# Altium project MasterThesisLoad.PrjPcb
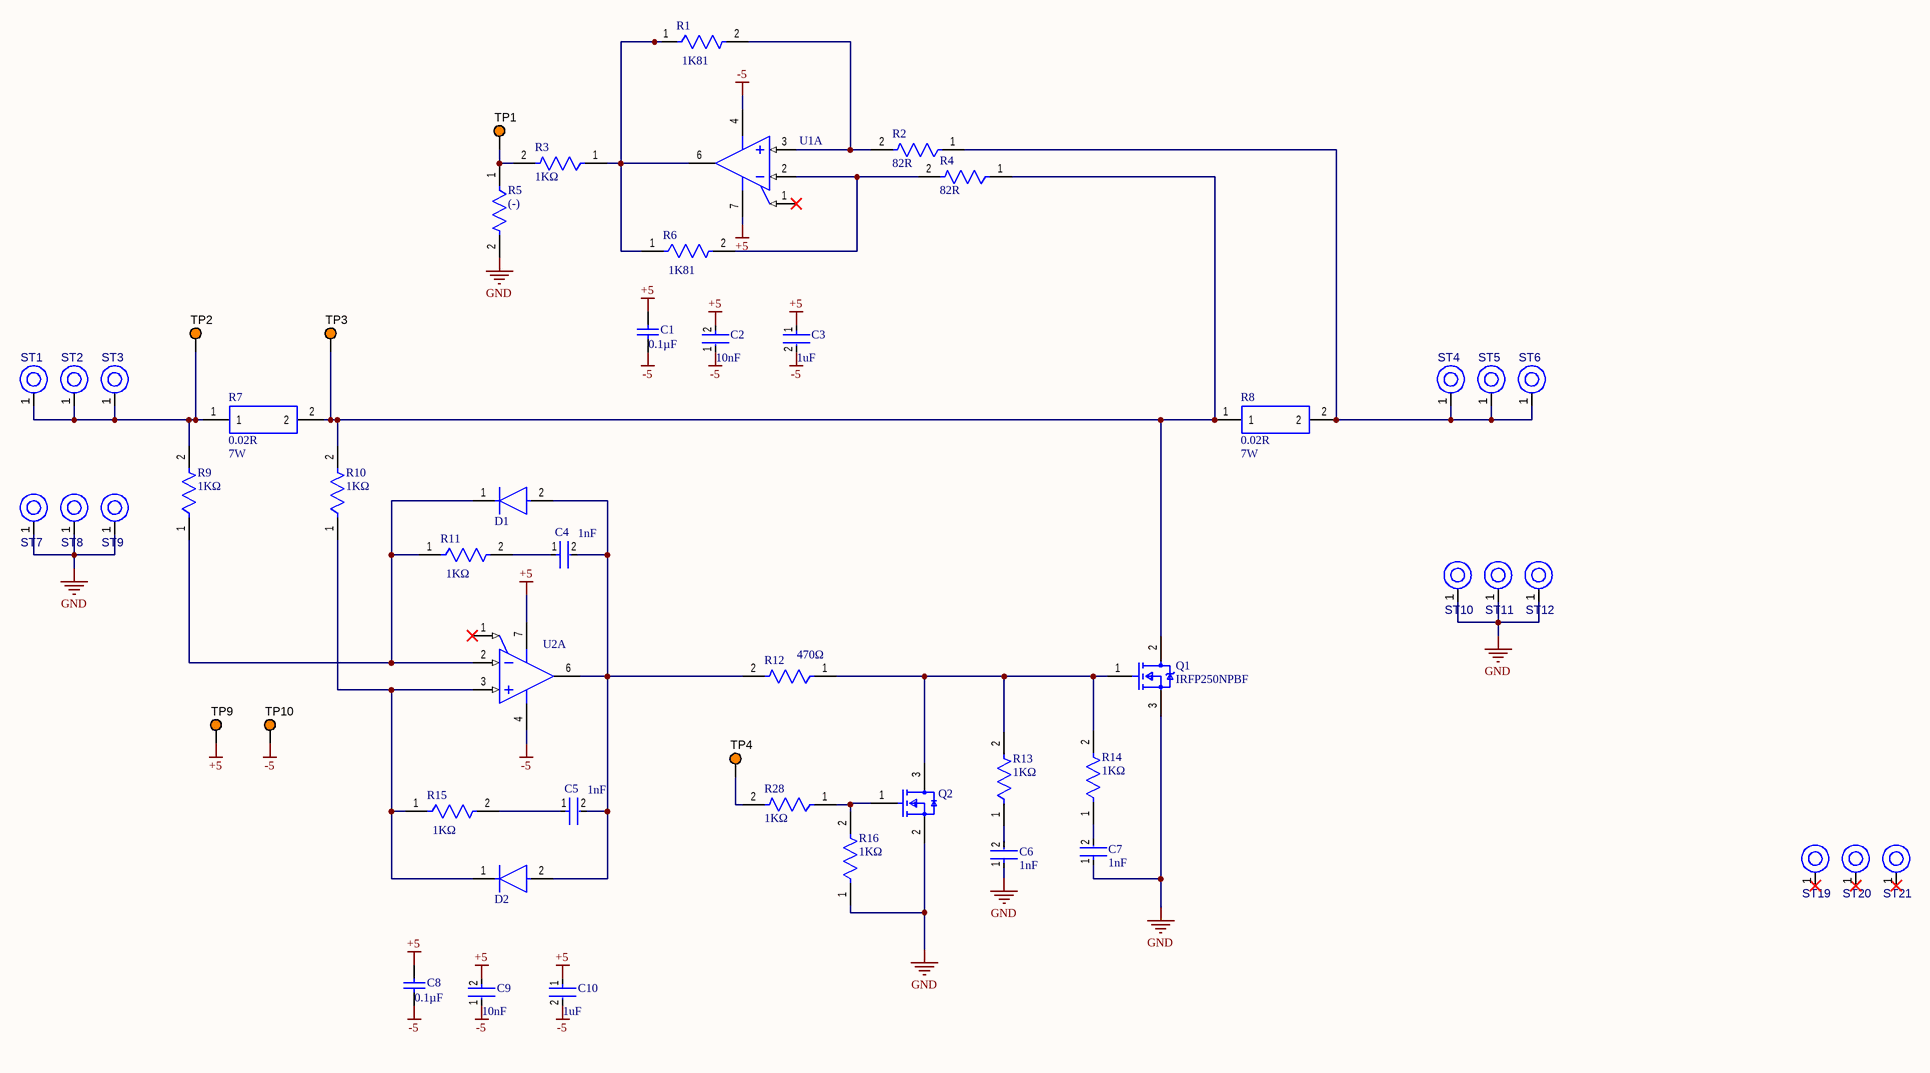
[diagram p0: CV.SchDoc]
CAGE_CODE: ?????; CONTRACT_NUMBER: <CONTRACT NO>; DOC_NO_ASSY_DWG: <ASSY DWG NO>; DOC_NO_BOM: <BOM DOC NO>; DOC_NO_FAB_DWG: <FAB DWG NO>; DOC_NO_SCH_DWG: <SCH DWG NO>; PCB_2_DEC_TOL: +/-.01; PCB_3_DEC_TOL: +/-.010; PCB_ANG_TOL: +/-1/2; PCB_ASSEMBLY_NO: <PCB ASSY NO>; PCB_CHECKER: - -----; PCB_CHECKER_APP_DATE: --/--/----; PCB_DESIGNER: - -----; PCB_DESIGNER_APP_DATE: --/--/----; PCB_DWG_NO: <PCB DWG NO>; PCB_ENGINEER: - -----; PCB_ENGINEER_APP_DATE: --/--/----; PCB_PART_NUMBER: <PCB PN>; PCB_REV: A; SCH_REV: A
2 sheets, 90 parts. Net scope: global (net labels, ports and power ports of the same name join across sheets).
Board file: PCB1.PcbDoc
Sheets:
  CV.SchDoc
  CC.SchDoc

## Sheet CV.SchDoc
size 431 x 279 mm; SheetNumber: 1; SheetTotal: 2; ENG_APP_DATE: --/--/--; DSN_APP_DATE: --/--/--; CHK_APP_DATE: --/--/--

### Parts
C1  Capacitance: 0.1µF  [SAMS-C0603-2_M]  (hidden comment: CL10B104KB8NNNC)
C2  Capacitance: 10nF  [FP-C1608-080-0_1-MFG]  (hidden comment: C1608X7R1H103M080AA)
C3  Capacitance: 1uF  [FP-0603-L_1_6_0_15-W_0_8-IPC_C]  (hidden comment: UMK107AB7105KA-T)
C4  Capacitance: 1nF  [FP-CL10-IPC_C]  (hidden comment: CL10B102KB8WPNC)
C5  Capacitance: 1nF  [FP-CL10-IPC_C]  (hidden comment: CL10B102KB8WPNC)
C6  Capacitance: 1nF  [FP-CL10-IPC_C]  (hidden comment: CL10B102KB8WPNC)
C7  Capacitance: 1nF  [FP-CL10-IPC_C]  (hidden comment: CL10B102KB8WPNC)
C8  Capacitance: 0.1µF  [SAMS-C0603-2_M]  (hidden comment: CL10B104KB8NNNC)
C9  Capacitance: 10nF  [FP-C1608-080-0_1-MFG]  (hidden comment: C1608X7R1H103M080AA)
C10  Capacitance: 1uF  [FP-0603-L_1_6_0_15-W_0_8-IPC_C]  (hidden comment: UMK107AB7105KA-T)
D1  BAS316,115  [FP-SOD323-IPC_A]  (value not drawn)
D2  BAS316,115  [FP-SOD323-IPC_A]  (value not drawn)
Q1  IRFP250NPBF  [FP-PG-TO247-3-MFG]
Q2  2N7002-7-F  [FP-SOT23-MFG]  (value not drawn)
R1  Resistance: 1K81  [FP-RT0603-MFG]  (hidden comment: RT0603FRE071KL)
R2  Resistance: 82R  [FP-RT0603-MFG]  (hidden comment: RT0603FRE071KL)
R3  Resistance: 1KΩ  [FP-RT0603-MFG]  (hidden comment: RT0603FRE071KL)
R4  Resistance: 82R  [FP-RT0603-MFG]  (hidden comment: RT0603FRE071KL)
R5  Resistance: (-)  [FP-RT0603-MFG]  (hidden comment: RT0603FRE071KL)
R6  Resistance: 1K81  [FP-RT0603-MFG]  (hidden comment: RT0603FRE071KL)
R7  value 0.02R  Power: 7W  [WSHM2818R0200FEA]  (hidden comment: WSHM2818R0200FEA)
R8  value 0.02R  Power: 7W  [WSHM2818R0200FEA]  (hidden comment: WSHM2818R0200FEA)
R9  Resistance: 1KΩ  [FP-RT0603-MFG]  (hidden comment: RT0603FRE071KL)
R10  Resistance: 1KΩ  [FP-RT0603-MFG]  (hidden comment: RT0603FRE071KL)
R11  Resistance: 1KΩ  [FP-RT0603-MFG]  (hidden comment: RT0603FRE071KL)
R12  value 470Ω  [FP-RT0603-MFG]  (hidden comment: RT0603FRE07470RL)
R13  Resistance: 1KΩ  [FP-RT0603-MFG]  (hidden comment: RT0603FRE071KL)
R14  Resistance: 1KΩ  [FP-RT0603-MFG]  (hidden comment: RT0603FRE071KL)
R15  Resistance: 1KΩ  [FP-RT0603-MFG]  (hidden comment: RT0603FRE071KL)
R16  Resistance: 1KΩ  [FP-RT0603-MFG]  (hidden comment: RT0603FRE071KL)
R28  Resistance: 1KΩ  [FP-RT0603-MFG]  (hidden comment: RT0603FRE071KL)
ST1  PTH-M2D5X5  [PTH-M2D5X5]  (value not drawn)
ST2  PTH-M2D5X5  [PTH-M2D5X5]  (value not drawn)
ST3  PTH-M2D5X5  [PTH-M2D5X5]  (value not drawn)
ST4  PTH-M2D5X5  [PTH-M2D5X5]  (value not drawn)
ST5  PTH-M2D5X5  [PTH-M2D5X5]  (value not drawn)
ST6  PTH-M2D5X5  [PTH-M2D5X5]  (value not drawn)
ST7  PTH-M2D5X5  [PTH-M2D5X5]  (value not drawn)
ST8  PTH-M2D5X5  [PTH-M2D5X5]  (value not drawn)
ST9  PTH-M2D5X5  [PTH-M2D5X5]  (value not drawn)
ST10  PTH-M2D5X5  [PTH-M2D5X5]  (value not drawn)
ST11  PTH-M2D5X5  [PTH-M2D5X5]  (value not drawn)
ST12  PTH-M2D5X5  [PTH-M2D5X5]  (value not drawn)
ST19  PTH-M2D5X5  [PTH-M2D5X5]  (value not drawn)
ST20  PTH-M2D5X5  [PTH-M2D5X5]  (value not drawn)
ST21  PTH-M2D5X5  [PTH-M2D5X5]  (value not drawn)
TP1  5003  [KSTN-5003]  (value not drawn)
TP2  5003  [KSTN-5003]  (value not drawn)
TP3  5003  [KSTN-5003]  (value not drawn)
TP4  5003  [KSTN-5003]  (value not drawn)
TP9  5003  [KSTN-5003]  (value not drawn)
TP10  5003  [KSTN-5003]  (value not drawn)
U1  LTC2050HVCS8#PBF  [LT-S8-8_L]  (value not drawn)  (part A of 2)
U2  LTC2050HVCS8#PBF  [LT-S8-8_L]  (value not drawn)  (part A of 2)

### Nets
+5: C1.2 C2.2 C3.1 C8.2 C9.2 C10.1 TP9.1 U1.7(V+) U2.7(V+)
-5: C1.1 C2.1 C3.2 C8.1 C9.1 C10.2 TP10.1 U1.4(V-) U2.4(V-)
GND: C6.1 C7.1 Q1.3(SOURCE) Q2.2(S) R5.2 R16.1 ST7.1(H1) ST8.1(H1) ST9.1(H1) ST10.1(H1) ST11.1(H1) ST12.1(H1)
NetC4_1: C4.1 R11.2
NetC4_2: C4.2 C5.2 D1.2(A) D2.2(A) R12.2 U2.6(OUT)
NetC5_1: C5.1 R15.2
NetC6_2: C6.2 R13.1
NetC7_2: C7.2 R14.1
NetD1_1: D1.1(C) R9.1 R11.1 U2.2(-IN)
NetD2_1: D2.1(C) R10.1 R15.1 U2.3(+IN)
NetQ1_1: Q1.1(GATE) Q2.3(D) R12.1 R13.2 R14.2
NetQ1_2: Q1.2(DRAIN) R4.1 R7.2 R8.1 R10.2 TP3.1
NetQ2_1: Q2.1(G) R16.2 R28.1
NetR1_1: R1.1 R3.1 R6.1 U1.6(OUT)
NetR1_2: R1.2 R2.2 U1.3(+IN)
NetR2_1: R2.1 R8.2 ST4.1(H1) ST5.1(H1) ST6.1(H1)
NetR3_2: R3.2 R5.1 TP1.1
NetR4_2: R4.2 R6.2 U1.2(-IN)
NetR7_1: R7.1 R9.2 ST1.1(H1) ST2.1(H1) ST3.1(H1) TP2.1
NetR28_2: R28.2 TP4.1

Not connected (* = marked no-connect by the designer): ST19 1(H1)*; ST20 1(H1)*; ST21 1(H1)*; U1 1(~{SHDN})*; U2 1(~{SHDN})*

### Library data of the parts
C1 C8 = CMP-2000-05332-1: Multi-layer Ceramic Capacitor, -55 to 125 degC, 2-Pin SMD (0603), RoHS, Tape and Reel; Manufacturer: Samsung Electro-Mechanics; Rated Voltage: 50V; Dielectric: X7R; Tolerance (%): ±10%
C2 C9 = CMP-08246-006703-1: Multilayer Ceramic Capacitors 10nF ±20% 50V X7R SMD 0603
C3 C10 = CMP-2000-07531-4: Ceramic Capacitor General Use 1uF ±10% 50V X7R 0603
C4-C7 = CMP-13271-004548-1: Cap Ceramic 1nF 50V X7R ±10% Pad SMD 0603 +125°C T/R
D1 D2 = CMP-14399-000012-1: DIODE GEN PURP 100V 250MA SOD323
Q1 = CMP-32901-000198-1: MOSFET N-CH 200V 30A TO-247AC; Rds On Max: 75mR; Input Capacitance: 2.159nF; Turn-Off Delay Time: 41ns; Max Power Dissipation: 214W; Turn-On Delay Time: 14ns; Gate to Source Voltage (Vgs): 20V; Element Configuration: Single
Q2 = CMP-2000-04929-2: MOSFET N-CH 60V 115MA SOT23-3; Turn-On Delay Time: 7ns; Turn-Off Delay Time: 11ns; Drain to Source Resistance: 7.5R; Rise Time: 3ns; Drain to Source Breakdown Voltage: 70V; Input Capacitance: 50pF; Number of Elements: 1; Power Dissipation: 540mW; Max Power Dissipation: 300mW; Fall Time: 5.6ns; Gate to Source Voltage (Vgs): 20V; Threshold Voltage: 2.5V; Element Configuration: Single
R1-R6 R9-R11 R13-R16 R28 = CMP-03412-005349-1: RES SMD 1K OHM 1% 1/10W 0603 Je tuspatny datasheet!!!; Manufacturer: Yageo; Manufacturer Part Number: RT0603FRE0710KL; Value: 1KΩ; Temperature Coefficient: 50 ppm/°C; Power Rating: 0.1W; Tolerance: 0.01; Voltage Rating: 75V; Max Power Dissipation: 100mW
R7 R8 = WSHM2818R0200FEA: Rezistory ke snímání proudu - SMD .02ohms 7watt 1%
R12 = CMP-03412-035774-1: RES 470 OHM 1/10W 1% SMD 0603; Manufacturer: Yageo; Power Rating: 0.1W; Tolerance: 0.01; Temperature Coefficient: 50 ppm/°C; Voltage Rating: 75V
ST1-ST12 ST19-ST21 = CMP-00028-00004-1: M2 PTH (2.5mm), 5mm pad
TP1-TP4 TP9 TP10 = CMP-002-00037-1: Test Point, Orange, Height 4.6 mm, Tail Length 3 mm, 1-Pin THD, RoHS; Manufacturer: Keystone
U1 U2 = CMP-0359-03372-2: Single Channel, Zero-Drift Operational Amplifier, 3 MHz Typical GBW, 2 V/us Typical SR, 2.7 to 11 V, 8-Pin SOIC (S8-8), Commercial, Pb-Free; Manufacturer: Linear Technology; GBW (MHz) Typical: 3; Vs Max (V): 11; Vos (mV) Typical: 0.0005; Is (mA) Typical: 0.8; Vs Min (V): 2.7; Channels (#): 1; SR (V/us) Typical: 2

## Sheet CC.SchDoc
size A3; SheetNumber: 2; SheetTotal: 2
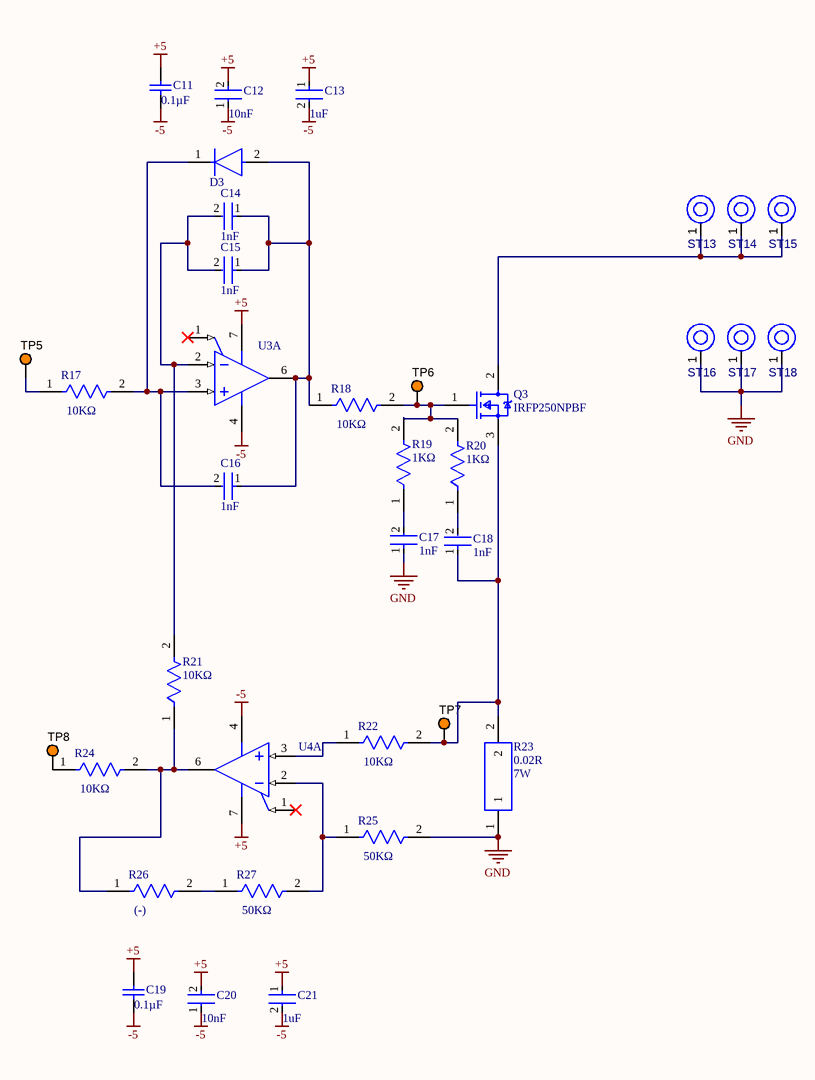
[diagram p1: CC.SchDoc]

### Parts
C11  Capacitance: 0.1µF  [SAMS-C0603-2_M]  (hidden comment: CL10B104KB8NNNC)
C12  Capacitance: 10nF  [FP-C1608-080-0_1-MFG]  (hidden comment: C1608X7R1H103M080AA)
C13  Capacitance: 1uF  [FP-0603-L_1_6_0_15-W_0_8-IPC_C]  (hidden comment: UMK107AB7105KA-T)
C14  Capacitance: 1nF  [FP-CL10-IPC_C]  (hidden comment: CL10B102KB8WPNC)
C15  Capacitance: 1nF  [FP-CL10-IPC_C]  (hidden comment: CL10B102KB8WPNC)
C16  Capacitance: 1nF  [FP-CL10-IPC_C]  (hidden comment: CL10B102KB8WPNC)
C17  Capacitance: 1nF  [FP-CL10-IPC_C]  (hidden comment: CL10B102KB8WPNC)
C18  Capacitance: 1nF  [FP-CL10-IPC_C]  (hidden comment: CL10B102KB8WPNC)
C19  Capacitance: 0.1µF  [SAMS-C0603-2_M]  (hidden comment: CL10B104KB8NNNC)
C20  Capacitance: 10nF  [FP-C1608-080-0_1-MFG]  (hidden comment: C1608X7R1H103M080AA)
C21  Capacitance: 1uF  [FP-0603-L_1_6_0_15-W_0_8-IPC_C]  (hidden comment: UMK107AB7105KA-T)
D3  BAS316,115  [FP-SOD323-IPC_A]  (value not drawn)
Q3  IRFP250NPBF  [FP-PG-TO247-3-MFG]
R17  Resistance: 10KΩ  [FP-RT0603-MFG]  (hidden comment: RT0603FRE071KL)
R18  Resistance: 10KΩ  [FP-RT0603-MFG]  (hidden comment: RT0603FRE071KL)
R19  Resistance: 1KΩ  [FP-RT0603-MFG]  (hidden comment: RT0603FRE071KL)
R20  Resistance: 1KΩ  [FP-RT0603-MFG]  (hidden comment: RT0603FRE071KL)
R21  Resistance: 10KΩ  [FP-RT0603-MFG]  (hidden comment: RT0603FRE071KL)
R22  Resistance: 10KΩ  [FP-RT0603-MFG]  (hidden comment: RT0603FRE071KL)
R23  value 0.02R  Power: 7W  [WSHM2818R0200FEA]  (hidden comment: WSHM2818R0200FEA)
R24  Resistance: 10KΩ  [FP-RT0603-MFG]  (hidden comment: RT0603FRE071KL)
R25  Resistance: 50KΩ  [FP-RT0603-MFG]  (hidden comment: RT0603FRE071KL)
R26  Resistance: (-)  [FP-RT0603-MFG]  (hidden comment: RT0603FRE071KL)
R27  Resistance: 50KΩ  [FP-RT0603-MFG]  (hidden comment: RT0603FRE071KL)
ST13  PTH-M2D5X5  [PTH-M2D5X5]  (value not drawn)
ST14  PTH-M2D5X5  [PTH-M2D5X5]  (value not drawn)
ST15  PTH-M2D5X5  [PTH-M2D5X5]  (value not drawn)
ST16  PTH-M2D5X5  [PTH-M2D5X5]  (value not drawn)
ST17  PTH-M2D5X5  [PTH-M2D5X5]  (value not drawn)
ST18  PTH-M2D5X5  [PTH-M2D5X5]  (value not drawn)
TP5  5003  [KSTN-5003]  (value not drawn)
TP6  5003  [KSTN-5003]  (value not drawn)
TP7  5003  [KSTN-5003]  (value not drawn)
TP8  5003  [KSTN-5003]  (value not drawn)
U3  LTC2050HVCS8#PBF  [LT-S8-8_L]  (value not drawn)  (part A of 2)
U4  LTC2050HVCS8#PBF  [LT-S8-8_L]  (value not drawn)  (part A of 2)

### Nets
+5: C11.2 C12.2 C13.1 C19.2 C20.2 C21.1 U3.7(V+) U4.7(V+)
-5: C11.1 C12.1 C13.2 C19.1 C20.1 C21.2 U3.4(V-) U4.4(V-)
GND: C17.1 R23.1 R25.2 ST16.1(H1) ST17.1(H1) ST18.1(H1)
NetC14_1: C14.1 C15.1 C16.1 D3.2(A) R18.1 U3.6(OUT)
NetC14_2: C14.2 C15.2 R21.2 U3.2(-IN)
NetC16_2: C16.2 D3.1(C) R17.2 U3.3(+IN)
NetC17_2: C17.2 R19.1
NetC18_1: C18.1 Q3.3(SOURCE) R22.2 R23.2 TP7.1
NetC18_2: C18.2 R20.1
NetQ3_1: Q3.1(GATE) R18.2 R19.2 R20.2 TP6.1
NetQ3_2: Q3.2(DRAIN) ST13.1(H1) ST14.1(H1) ST15.1(H1)
NetR17_1: R17.1 TP5.1
NetR21_1: R21.1 R24.2 R26.1 U4.6(OUT)
NetR22_1: R22.1 U4.3(+IN)
NetR24_1: R24.1 TP8.1
NetR25_1: R25.1 R27.2 U4.2(-IN)
NetR26_2: R26.2 R27.1

Not connected (* = marked no-connect by the designer): U3 1(~{SHDN})*; U4 1(~{SHDN})*

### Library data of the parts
C11 C19 = CMP-2000-05332-1: as C1 on sheet CV
C12 C20 = CMP-08246-006703-1: as C2 on sheet CV
C13 C21 = CMP-2000-07531-4: as C3 on sheet CV
C14-C18 = CMP-13271-004548-1: as C4 on sheet CV
D3 = CMP-14399-000012-1: DIODE GEN PURP 100V 250MA SOD323
Q3 = CMP-32901-000198-1: as Q1 on sheet CV
R17-R22 R24-R27 = CMP-03412-005349-1: as R1 on sheet CV
R23 = WSHM2818R0200FEA: as R7 on sheet CV
ST13-ST18 = CMP-00028-00004-1: M2 PTH (2.5mm), 5mm pad
TP5-TP8 = CMP-002-00037-1: as TP1 on sheet CV
U3 U4 = CMP-0359-03372-2: as U1 on sheet CV

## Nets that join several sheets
+5: CV (9 pins), CC (8 pins)
-5: CV (9 pins), CC (8 pins)
GND: CV (12 pins), CC (6 pins)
